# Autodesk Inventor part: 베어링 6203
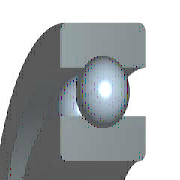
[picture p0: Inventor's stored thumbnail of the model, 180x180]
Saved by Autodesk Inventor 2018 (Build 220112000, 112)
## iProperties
IsCustomPart: 1
Created: 2012-02
Part Number: 베어링 6203
Material: 강철, 연강
Description: 깊은 그루브 볼 베어링
Document SubType Name: Modeling
Standard: KS B 2023
Designer: mduedu
Standards Organization: KS
Language: ko-KR
Size Designation: 6203 - 17 x 40 x 12
Categories: <MemberInstance><Categories><Category DisplayName="샤프트 부품" InternalName="7f7aeb1f-a693-4053-b835-cee3144e0d98" Mnemonic="SHFT"><Category DisplayName="베어링" Inter
Density: 1 g/cm^3
Appearance: 노란색
Author: mduedu
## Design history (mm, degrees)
sketch "스케치" dims "d0" = 5.98 (= -0.26 x WD + 0.26 x BD)
  geometry: L1 (3.01, 14.25)-(8.99, 14.25); L2 (6, 14.25)-(6, 11.26); L3 (6, 14.25)-(6, 17.24); L4 (3.778, 12.249)-(0, 12.249); L5 (0, 8.5)-(12, 8.5); L6 (3.778, 16.251)-(0, 16.251); L7 (0, 20)-(12, 20); L8 (12, 8.5)-(12, 12.249); L9 (8.222, 12.249)-(12, 12.249); L10 (8.222, 16.251)-(12, 16.251); L11 (12, 20)-(12, 16.251); L12 (-1.4, 0)-(8.4, 0) reference; L13 (0, -0.3)-(0, 5.3) reference
  constraints: 22 end point, 4 point on line, 2 collinear, 2 perpendicular, 2 symmetric about line, 1 midpoint, 1 parallel, 14 other
  dimensions: "d9" = 17 diameter of L5 L12 (= WD); "d11" = 40 diameter of L7 L12 (= BD); "d12" = 12 distance between parallel lines of L8 L13 (= KB); "d13" = 24.498 diameter of L9 L12 (= 0.326 x BD + 0.674 x WD)
revolve "본체" stored, may be unused: angle "d6" = 90 deg
revolve "볼" stored, may be unused: angle "d7" = 90 deg
pattern_circular "IDS_ARRAYBALL[SIMPL:T]" dims angle "d3" = 360 deg
body "Solid1"
fillet "모깎기1" dims "d1" = 0.6 (= KRS)
other parameters: "WD" = 17 [user parameter; used in 5 equation terms], "BD" = 40 [user parameter; used in 5 equation terms], "KB" = 12 [user parameter; used in 1 equation term], "KRS" = 0.6 [user parameter; used in 1 equation term], "d4" = 0, "d5" = 0, "d8" = 0, "d14" = 0, "d15" = 0, "BBA" = 0 [user parameter], "BC0" = 4750000 [user parameter], "BC" = 9560000 [user parameter], "WR" = 8.5 (= 0.5 x WD) [user parameter]
